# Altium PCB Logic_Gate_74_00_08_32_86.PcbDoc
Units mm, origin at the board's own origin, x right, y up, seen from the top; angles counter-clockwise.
Board outline 84.89 x 42.16 mm, 2 copper layers (Top Layer, Bottom Layer); 12 components, 18 nets, 61 pads, 0 vias.
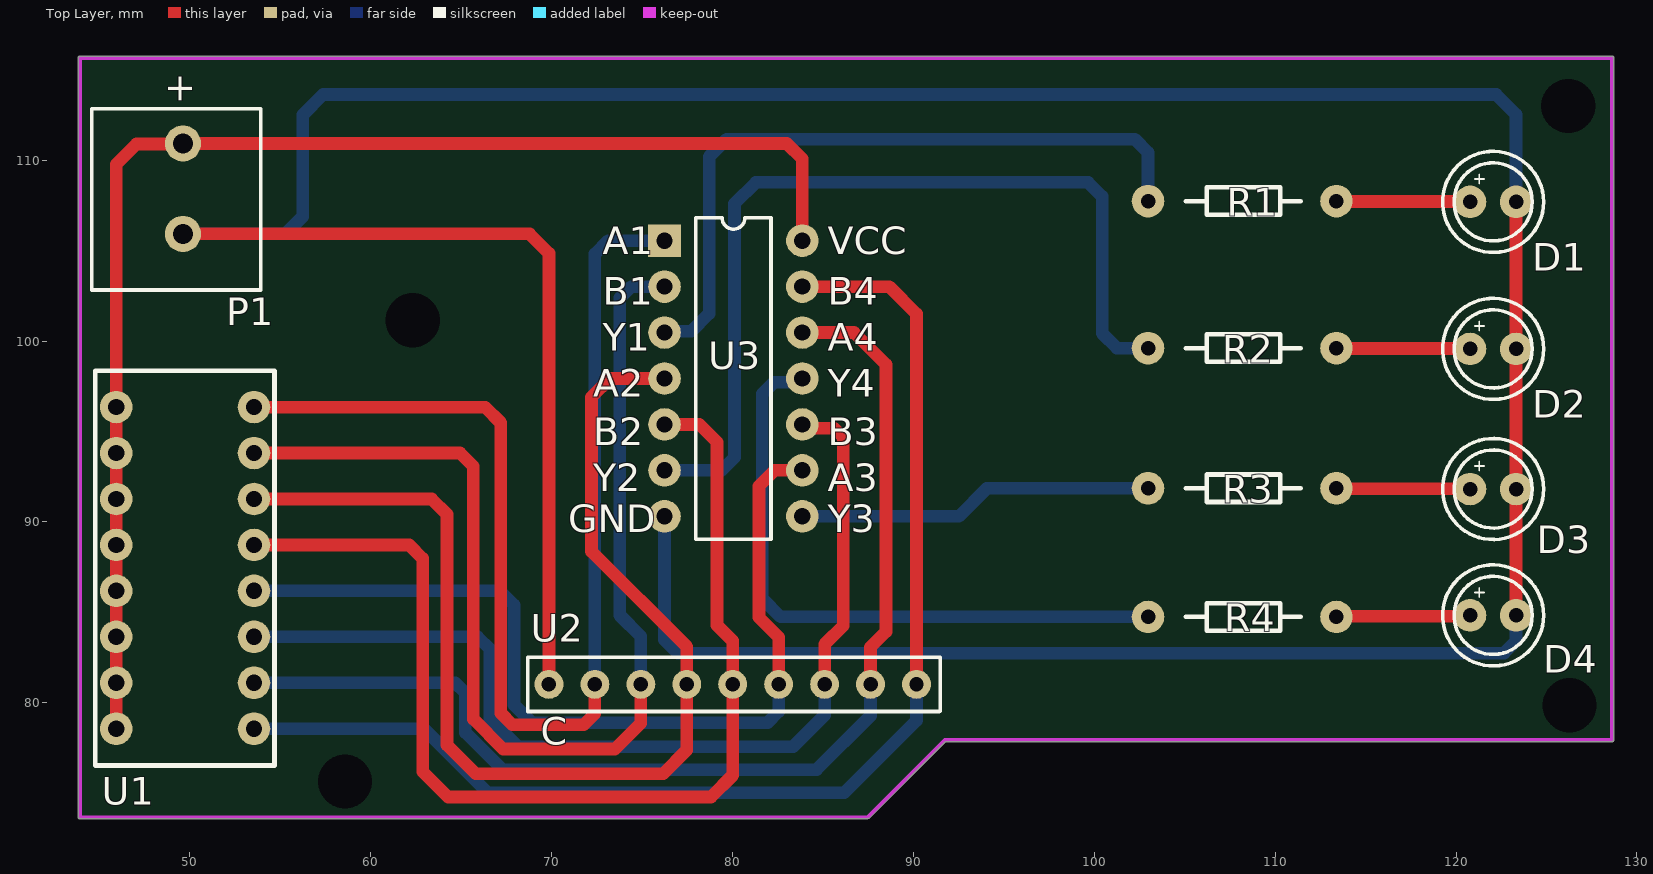
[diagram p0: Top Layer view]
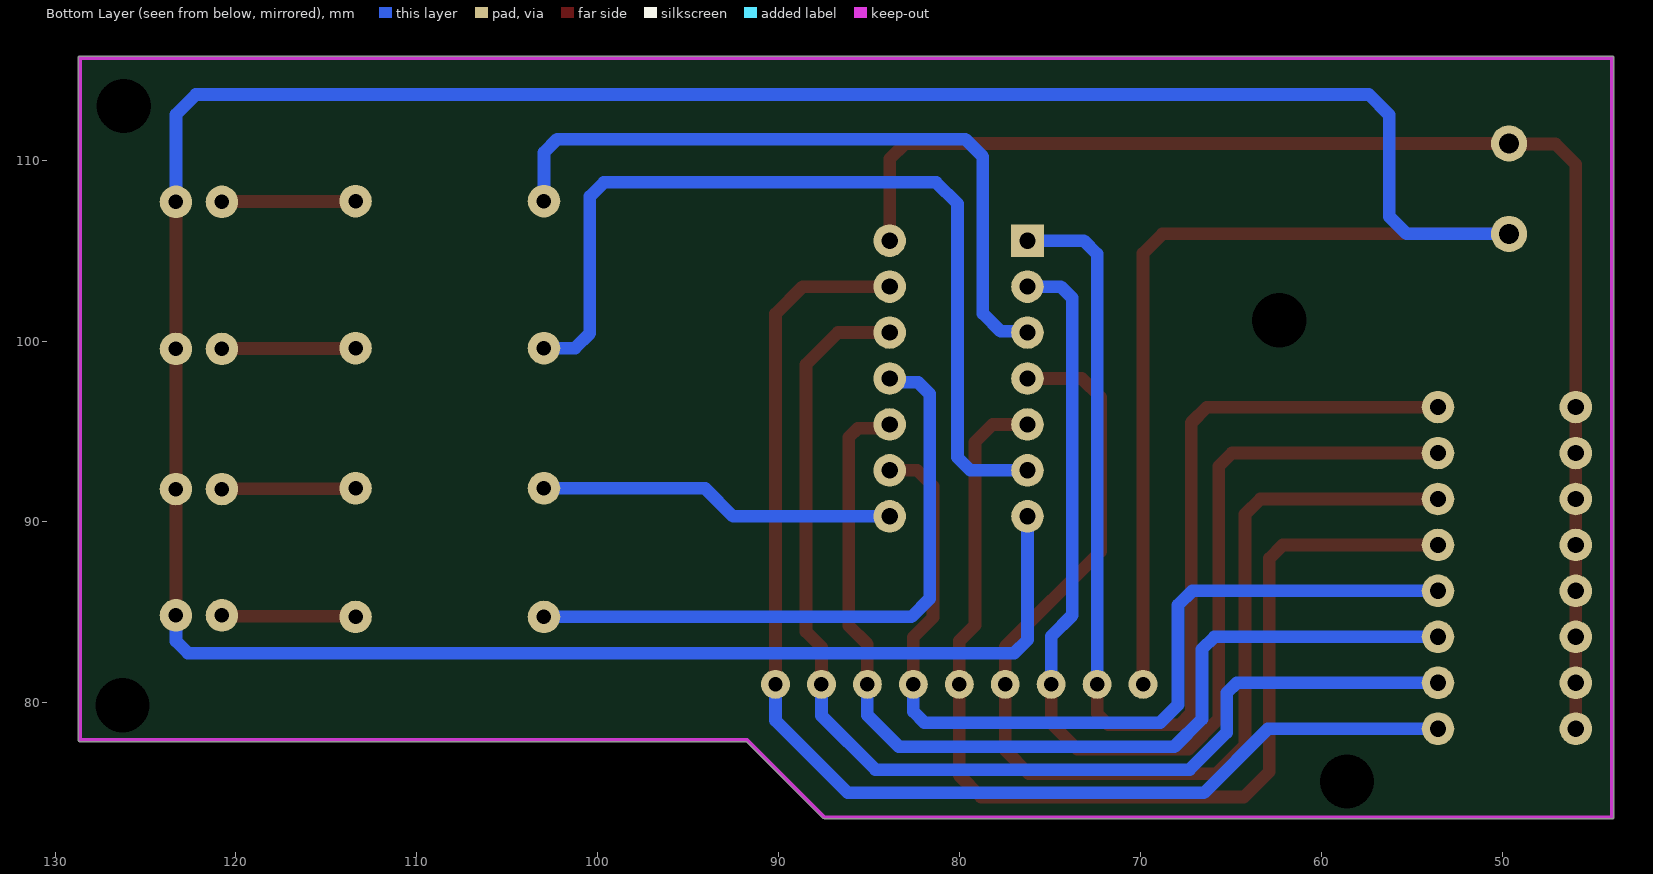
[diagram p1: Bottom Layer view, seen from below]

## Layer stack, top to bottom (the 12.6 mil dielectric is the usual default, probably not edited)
Top Solder: solder mask 0.0102, Solder Resist, Dk 3.5
Top Layer: signal copper 0.0356
Dielectric 1: dielectric 0.32, FR-4, Dk 4.8
Bottom Layer: signal copper 0.0356
Bottom Solder: solder mask 0.0102, Solder Resist, Dk 3.5

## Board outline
43.927,73.585 cw(c43.927,73.685) 43.826,73.685 43.826,115.649 cw(c43.927,115.649) 43.927,115.749 128.619,115.749 cw(c128.619,115.649) 128.72,115.649 128.72,115.586 128.72,77.95 cw(c128.619,77.95) 128.603,77.851 128.586,77.85 91.776,77.85 87.54,73.614 87.469,73.585

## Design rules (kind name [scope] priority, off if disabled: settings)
Clearance [All] p1: gap=0.254 ignorepadtopadclearanceinfootprint=FALSE
PolygonConnect [All] p1: connectstyle=Relief reliefconductorwidth=0.254 reliefentries=4 polygonreliefangle="90 Angle" airgapwidth=0.254
RoutingVias [All] p1: holewidth=0.711 width=1.27 viastyle="Through Hole" minholewidth=0.711 minwidth=1.27 maxholewidth=0.711 maxwidth=1.27
SolderMaskExpansion [All] p1: expansion=0.102 istentingtop=FALSE
SupplyNets "Schematic Supply Nets_1" [InNet('GND')] p1: voltage=0.000
SupplyNets "Schematic Supply Nets" [InNet('5v0')] p2: voltage=0.000
Width [All] p1: maxlimit=0.9 minlimit=0.2 preferedwidth=0.7 minimp=50.000000 maximp=50.000000 favimp=50.000000
30 further rules are at their usual default settings.

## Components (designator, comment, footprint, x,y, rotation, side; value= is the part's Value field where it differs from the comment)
D1 "LED0" LED_5M 122.047,107.696 r0 top
D2 "LED0" LED_5M 122.047,99.568 r0 top
D3 "LED0" LED_5M 122.047,91.821 r0 top
D4 "LED0" LED_5M 122.047,84.836 r0 top
P1 "Input" K300_5_2 49.784,107.696 r270 top
R1 "Res1" Resistor 108.331,107.696 r0 top value=1K
R2 "Res1" Resistor 108.331,99.568 r0 top value=1K
R3 "Res1" Resistor 108.331,91.821 r0 top value=1K
R4 "Res1" Resistor 108.331,84.709 r0 top value=1K
U1 "DIPSW8" DIPSW8 49.784,92.583 r270 top
U2 "ArrayRes_10K" ArrayRes_10K 80.022,81.058 r0 top
U3 "74HC08" 74HC08 76.24,105.552 r0 top

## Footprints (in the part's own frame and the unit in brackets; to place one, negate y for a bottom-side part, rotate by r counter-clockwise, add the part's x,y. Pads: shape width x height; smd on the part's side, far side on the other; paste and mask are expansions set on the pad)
74HC08 [mm]
  rect 1.8x1.8 hole 0.9: 1(0,0)
  round 1.8 hole 0.9: 2(0,-2.54) 3(0,-5.08) 4(0,-7.62) 5(0,-10.16) 6(0,-12.7) 7(0,-15.24) 8(7.62,-15.24) 9(7.62,-12.7) 10(7.62,-10.16) 11(7.62,-7.62) 12(7.62,-5.08) 13(7.62,-2.54) 14(7.62,0)
  silkscreen extent 1.73,-16.51 5.89,1.27
ArrayRes_10K [mm]
  round 1.6 hole 0.8: 1(-10.172,-0.032) 2(-7.632,-0.032) 3(-5.092,-0.032) 4(-2.552,-0.032) 5(-0.012,-0.032) 6(2.528,-0.032) 7(5.068,-0.032) 8(7.608,-0.032) 9(10.148,-0.032)
  silkscreen extent -11.35,-1.54 11.47,1.47
DIPSW8 [mm]
  round 1.8 hole 0.9: 1(-3.768,-3.859) 2(-3.768,3.761) 3(-1.228,-3.859) 4(-1.228,3.761) 5(1.312,-3.859) 6(1.312,3.761) 7(3.852,-3.859) 8(3.852,3.761) 9(6.392,-3.859) 10(6.392,3.761) 11(8.932,-3.859) 12(8.932,3.761) 13(11.472,-3.859) 14(11.472,3.761) 15(14.012,-3.859) 16(14.012,3.761)
  silkscreen extent -5.77,-5.01 16.05,4.89
K300_5_2 [mm]
  round 2 hole 1.1: 1(-3.231,-0.167) 2(1.769,-0.167)
  silkscreen extent -5.15,-5.21 4.87,4.13
LED_5M [mm]
  round 1.8 hole 0.8: 1(-1.27,0) 2(1.27,0)
  silkscreen extent -2.79,-2.79 2.79,2.79
Resistor [mm]
  round 1.8 hole 0.8: 1(-5.361,0.043) 2(5.056,0.043)
  silkscreen extent -3.26,-0.72 3.09,0.8

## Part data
D1 D2 D3 D4: "Typical INFRARED GaAs LED"
P1: library part "Header 2", "Header, 2-Pin"
R1 R2 R3 R4: "Resistor"

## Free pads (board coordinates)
  round 0 hole 3: ""(58.572,75.656) ""(62.32,101.153) ""(126.203,112.996) ""(126.275,79.871)

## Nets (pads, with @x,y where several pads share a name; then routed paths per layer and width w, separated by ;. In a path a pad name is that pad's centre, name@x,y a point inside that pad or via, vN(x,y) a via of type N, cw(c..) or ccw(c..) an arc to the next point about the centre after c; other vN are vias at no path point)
5v0: P1.1 U1.1 U1.3 U1.5 U1.7 U1.9 U1.11 U1.13 U1.15 U3.14 | length 74.5
  Top Layer w0.7: U1.15 U1.13 U1.11 U1.9 U1.7 U1.5 U1.3 U1.1 45.925,109.77 47.051,110.897 49.587,110.897 P1.1 83,110.927 83.86,110.066 U3.14
A1: U1.2 U2.2 U3.1 | length 65.3
  Top Layer w0.7: U1.2 66.319,96.351 67.186,95.484 67.186,79.435 67.839,78.782 71.763,78.782 72.39,79.409 U2.2
  Bottom Layer w0.7: U2.2 72.39,104.811 73.132,105.552 U3.1
A2: U1.6 U2.4 U3.4 | length 64.4
  Top Layer w0.7: U1.6 63.366,91.271 64.211,90.426 64.211,77.671 65.81,76.072 76.154,76.072 77.47,77.388 U2.4 77.47,83.107 72.206,88.37 72.206,96.901 73.237,97.932 U3.4
A3: U1.10 U2.6 U3.9 | length 51.2
  Top Layer w0.7: U2.6 82.55,83.636 81.459,84.726 81.459,91.981 82.33,92.852 U3.9
  Bottom Layer w0.7: U1.10 67.132,86.191 67.917,85.406 67.917,79.897 68.915,78.899 81.932,78.899 82.55,79.517 U2.6
A4: U1.14 U2.8 U3.12 | length 63.7
  Top Layer w0.7: U3.12 86.713,100.472 88.482,98.703 88.482,83.935 87.63,83.083 U2.8
  Bottom Layer w0.7: U1.14 64.666,81.111 65.232,80.545 65.232,78.355 67.276,76.311 84.651,76.311 87.63,79.289 U2.8
B1: U1.4 U2.3 U3.2 | length 63.6
  Top Layer w0.7: U1.4 64.929,93.811 65.67,93.071 65.67,79.102 67.32,77.452 73.495,77.452 74.93,78.888 U2.3
  Bottom Layer w0.7: U2.3 74.93,83.679 73.765,84.844 73.765,102.378 74.399,103.012 U3.2
B2: U1.8 U2.5 U3.5 | length 61.7
  Top Layer w0.7: U1.8 62.126,88.731 62.871,87.986 62.871,76.203 64.275,74.799 78.812,74.799 80.01,75.997 U2.5 80.01,83.423 79.143,84.29 79.143,94.416 78.167,95.392 U3.5
B3: U1.12 U2.7 U3.10 | length 55.4
  Top Layer w0.7: U3.10 84.071,95.182 85.619,95.182 86.13,94.671 86.13,84.279 85.09,83.239 U2.7
  Bottom Layer w0.7: U1.12 65.907,83.651 66.591,82.967 66.591,79.108 68.125,77.574 83.35,77.574 85.09,79.314 U2.7
B4: U1.16 U2.9 U3.13 | length 69.2
  Top Layer w0.7: U3.13 88.662,103.012 90.17,101.504 U2.9
  Bottom Layer w0.7: U1.16 62.942,78.571 66.488,75.026 86.17,75.026 90.17,79.026 U2.9
GND: D1.2 D2.2 D3.2 D4.2 P1.2 U2.1 U3.7 | length 208.7
  Top Layer w0.7: P1.2 68.774,105.927 69.85,104.851 U2.1 ; D4.2 D3.2 D2.2 D1.2
  Bottom Layer w0.7: P1.2 55.272,105.927 56.237,106.892 56.237,112.504 57.367,113.634 122.214,113.634 123.317,112.53 D1.2 ; U3.7 76.24,83.483 76.974,82.75 122.658,82.75 123.317,83.409 D4.2
NetD1_1: D1.1 R1.2 | length 7.4
  Top Layer w0.7: R1.2 113.409,107.717 120.756,107.717 D1.1
NetD2_1: D2.1 R2.2 | length 7.4
  Top Layer w0.7: R2.2 113.409,99.589 120.756,99.589 D2.1
NetD3_1: D3.1 R3.2 | length 7.4
  Top Layer w0.7: R3.2 113.409,91.842 120.756,91.842 D3.1
NetD4_1: D4.1 R4.2 | length 7.4
  Top Layer w0.7: R4.2 113.429,84.794 120.735,84.794 D4.1
Y1: R1.1 U3.3 | length 39.2
  Bottom Layer w0.7: U3.3 76.313,100.545 77.725,100.545 78.707,101.527 78.707,110.192 79.673,111.157 102.24,111.157 102.97,110.427 R1.1
Y2: R2.1 U3.6 | length 49.8
  Bottom Layer w0.7: U3.6 79.391,92.852 80.112,93.573 80.112,107.599 81.287,108.774 99.655,108.774 100.437,107.992 100.437,100.433 101.258,99.611 R2.1
Y3: R3.1 U3.8 | length 19.8
  Bottom Layer w0.7: U3.8 92.514,90.312 94.066,91.864 R3.1
Y4: R4.1 U3.11 | length 35.6
  Bottom Layer w0.7: U3.11 83.65,97.722 82.281,97.722 81.641,97.082 81.641,85.768 82.657,84.752 R4.1

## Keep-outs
Keep-Out Layer:
  lines w0.2: 128.586,77.95 91.734,77.95 87.469,73.685 43.927,73.685 43.927,115.649 128.619,115.649 ; 128.619,77.95 128.619,115.586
